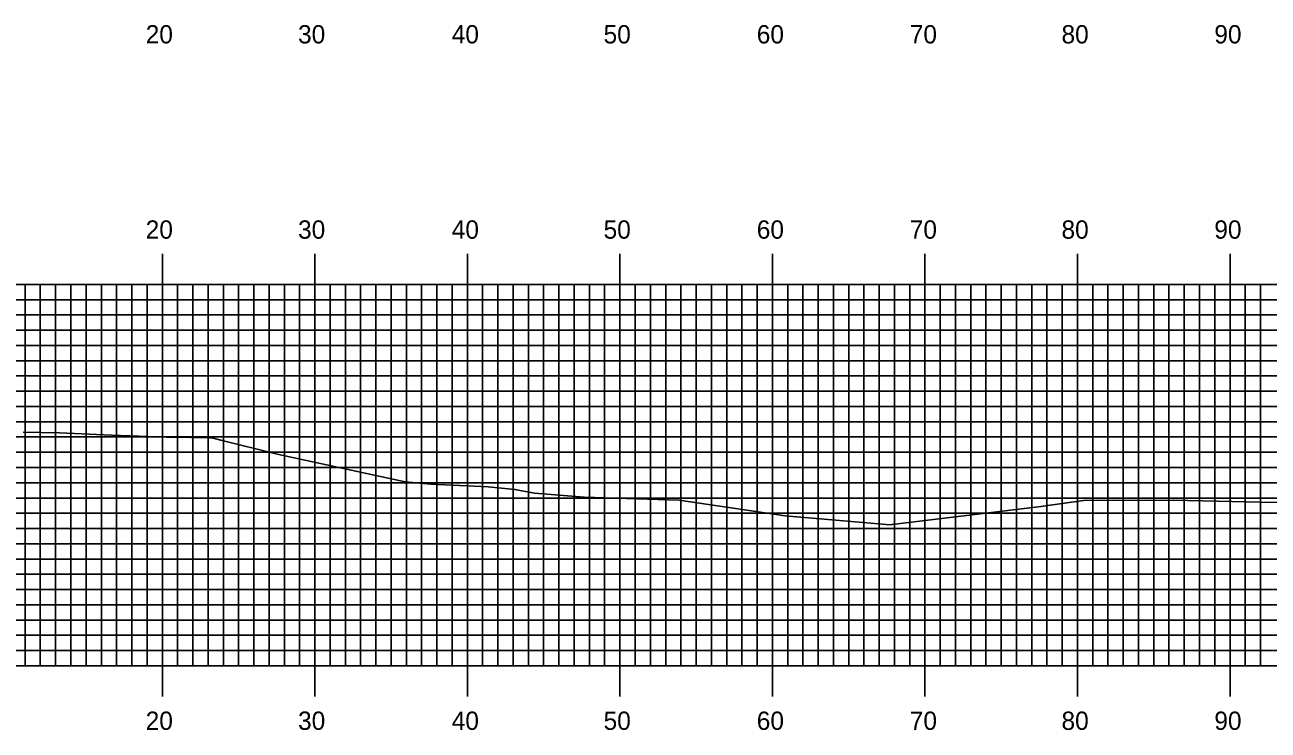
# Model space of a CAD drawing. Extents: x 851300 to 851643, y 366898 to 367118.
# Drawn here: x 851476.5 to 851558, y 366997.3 to 367043.5 of the extents above; entities that cross this region are included whole.
import ezdxf

# ---------------------------------------------------------------- set-up
doc = ezdxf.new("R2010")
doc.units = 0
for name, color, linetype in [('H_V ANNOTATION', 7, 'Continuous'), ('MAJOR', 7, 'Continuous'), ('MINOR', 7, 'Continuous'), ('S_Roadway_Centerline', 7, 'Continuous')]:
    doc.layers.add(name, color=color, linetype=linetype)

msp = doc.modelspace()

# ---------------------------------------------------------------- linework, layer by layer
at = {"layer": 'MAJOR'}
for p, q in [((851485.505, 367028.477), (851485.505, 367026.473)), ((851495.505, 367028.477), (851495.505, 367026.473)), ((851505.505, 367028.477), (851505.505, 367026.473)), ((851515.505, 367028.477), (851515.505, 367026.473)), ((851525.505, 367028.477), (851525.505, 367026.473)), ((851535.505, 367028.477), (851535.505, 367026.473)), ((851545.505, 367028.477), (851545.505, 367026.473)), ((851555.505, 367028.477), (851555.505, 367026.473)), ((851325.505, 367026.473), (851605.505, 367026.473)), ((851325.505, 367026.473), (851605.505, 367026.473)), ((851485.505, 367001.473), (851485.505, 367026.473)), ((851495.505, 367001.473), (851495.505, 367026.473)), ((851505.505, 367001.473), (851505.505, 367026.473)), ((851515.505, 367001.473), (851515.505, 367026.473)), ((851525.505, 367001.473), (851525.505, 367026.473)), ((851535.505, 367001.473), (851535.505, 367026.473)), ((851545.505, 367001.473), (851545.505, 367026.473)), ((851555.505, 367001.473), (851555.505, 367026.473)), ((851325.505, 367021.473), (851605.505, 367021.473)), ((851325.505, 367016.473), (851605.505, 367016.473)), ((851325.505, 367011.473), (851605.505, 367011.473)), ((851325.505, 367006.473), (851605.505, 367006.473)), ((851325.505, 367001.473), (851605.505, 367001.473)), ((851325.505, 367001.473), (851605.505, 367001.473)), ((851485.505, 366999.469), (851485.505, 367001.473)), ((851495.505, 366999.469), (851495.505, 367001.473)), ((851505.505, 366999.469), (851505.505, 367001.473)), ((851515.505, 366999.469), (851515.505, 367001.473)), ((851525.505, 366999.469), (851525.505, 367001.473)), ((851535.505, 366999.469), (851535.505, 367001.473)), ((851545.505, 366999.469), (851545.505, 367001.473)), ((851555.505, 366999.469), (851555.505, 367001.473))]:
    msp.add_line(p, q, dxfattribs=at)
at = {"layer": 'MINOR'}
for p, q in [((851476.505, 367001.473), (851476.505, 367026.473)), ((851477.505, 367001.473), (851477.505, 367026.473)), ((851478.505, 367001.473), (851478.505, 367026.473)), ((851479.505, 367001.473), (851479.505, 367026.473)), ((851480.505, 367001.473), (851480.505, 367026.473)), ((851481.505, 367001.473), (851481.505, 367026.473)), ((851482.505, 367001.473), (851482.505, 367026.473)), ((851483.505, 367001.473), (851483.505, 367026.473)), ((851484.505, 367001.473), (851484.505, 367026.473)), ((851486.505, 367001.473), (851486.505, 367026.473)), ((851487.505, 367001.473), (851487.505, 367026.473)), ((851488.505, 367001.473), (851488.505, 367026.473)), ((851489.505, 367001.473), (851489.505, 367026.473)), ((851490.505, 367001.473), (851490.505, 367026.473)), ((851491.505, 367001.473), (851491.505, 367026.473)), ((851492.505, 367001.473), (851492.505, 367026.473)), ((851493.505, 367001.473), (851493.505, 367026.473)), ((851494.505, 367001.473), (851494.505, 367026.473)), ((851496.505, 367001.473), (851496.505, 367026.473)), ((851497.505, 367001.473), (851497.505, 367026.473)), ((851498.505, 367001.473), (851498.505, 367026.473)), ((851499.505, 367001.473), (851499.505, 367026.473)), ((851500.505, 367001.473), (851500.505, 367026.473)), ((851501.505, 367001.473), (851501.505, 367026.473)), ((851502.505, 367001.473), (851502.505, 367026.473)), ((851503.505, 367001.473), (851503.505, 367026.473)), ((851504.505, 367001.473), (851504.505, 367026.473)), ((851506.505, 367001.473), (851506.505, 367026.473)), ((851507.505, 367001.473), (851507.505, 367026.473)), ((851508.505, 367001.473), (851508.505, 367026.473)), ((851509.505, 367001.473), (851509.505, 367026.473)), ((851510.505, 367001.473), (851510.505, 367026.473)), ((851511.505, 367001.473), (851511.505, 367026.473)), ((851512.505, 367001.473), (851512.505, 367026.473)), ((851513.505, 367001.473), (851513.505, 367026.473)), ((851514.505, 367001.473), (851514.505, 367026.473)), ((851516.505, 367001.473), (851516.505, 367026.473)), ((851517.505, 367001.473), (851517.505, 367026.473)), ((851518.505, 367001.473), (851518.505, 367026.473)), ((851519.505, 367001.473), (851519.505, 367026.473)), ((851520.505, 367001.473), (851520.505, 367026.473)), ((851521.505, 367001.473), (851521.505, 367026.473)), ((851522.505, 367001.473), (851522.505, 367026.473)), ((851523.505, 367001.473), (851523.505, 367026.473)), ((851524.505, 367001.473), (851524.505, 367026.473)), ((851526.505, 367001.473), (851526.505, 367026.473)), ((851527.505, 367001.473), (851527.505, 367026.473)), ((851528.505, 367001.473), (851528.505, 367026.473)), ((851529.505, 367001.473), (851529.505, 367026.473)), ((851530.505, 367001.473), (851530.505, 367026.473)), ((851531.505, 367001.473), (851531.505, 367026.473)), ((851532.505, 367001.473), (851532.505, 367026.473)), ((851533.505, 367001.473), (851533.505, 367026.473)), ((851534.505, 367001.473), (851534.505, 367026.473)), ((851536.505, 367001.473), (851536.505, 367026.473)), ((851537.505, 367001.473), (851537.505, 367026.473)), ((851538.505, 367001.473), (851538.505, 367026.473)), ((851539.505, 367001.473), (851539.505, 367026.473)), ((851540.505, 367001.473), (851540.505, 367026.473)), ((851541.505, 367001.473), (851541.505, 367026.473)), ((851542.505, 367001.473), (851542.505, 367026.473)), ((851543.505, 367001.473), (851543.505, 367026.473)), ((851544.505, 367001.473), (851544.505, 367026.473)), ((851546.505, 367001.473), (851546.505, 367026.473)), ((851547.505, 367001.473), (851547.505, 367026.473)), ((851548.505, 367001.473), (851548.505, 367026.473)), ((851549.505, 367001.473), (851549.505, 367026.473)), ((851550.505, 367001.473), (851550.505, 367026.473)), ((851551.505, 367001.473), (851551.505, 367026.473)), ((851552.505, 367001.473), (851552.505, 367026.473)), ((851553.505, 367001.473), (851553.505, 367026.473)), ((851554.505, 367001.473), (851554.505, 367026.473)), ((851556.505, 367001.473), (851556.505, 367026.473)), ((851557.505, 367001.473), (851557.505, 367026.473)), ((851325.505, 367025.473), (851605.505, 367025.473)), ((851325.505, 367024.473), (851605.505, 367024.473)), ((851325.505, 367023.473), (851605.505, 367023.473)), ((851325.505, 367022.473), (851605.505, 367022.473)), ((851325.505, 367020.473), (851605.505, 367020.473)), ((851325.505, 367019.473), (851605.505, 367019.473)), ((851325.505, 367018.473), (851605.505, 367018.473)), ((851325.505, 367017.473), (851605.505, 367017.473)), ((851325.505, 367015.473), (851605.505, 367015.473)), ((851325.505, 367014.473), (851605.505, 367014.473)), ((851325.505, 367013.473), (851605.505, 367013.473)), ((851325.505, 367012.473), (851605.505, 367012.473)), ((851325.505, 367010.473), (851605.505, 367010.473)), ((851325.505, 367009.473), (851605.505, 367009.473)), ((851325.505, 367008.473), (851605.505, 367008.473)), ((851325.505, 367007.473), (851605.505, 367007.473)), ((851325.505, 367005.473), (851605.505, 367005.473)), ((851325.505, 367004.473), (851605.505, 367004.473)), ((851325.505, 367003.473), (851605.505, 367003.473)), ((851325.505, 367002.473), (851605.505, 367002.473))]:
    msp.add_line(p, q, dxfattribs=at)
at = {"layer": 'S_Roadway_Centerline'}
msp.add_lwpolyline([(851476.378, 367016.793), (851478.759, 367016.736), (851482.162, 367016.603), (851485.758, 367016.465), (851486.137, 367016.461), (851488.621, 367016.408), (851488.828, 367016.404), (851489.35, 367016.265), (851493.039, 367015.342), (851501.426, 367013.537), (851503.117, 367013.378), (851506.86, 367013.209), (851508.62, 367013.037), (851509.901, 367012.791), (851513.153, 367012.523), (851519.385, 367012.325), (851526.343, 367011.304), (851533.224, 367010.718), (851533.354, 367010.747), (851543.109, 367011.911), (851545.903, 367012.303), (851546.352, 367012.321), (851548.587, 367012.311), (851551.78, 367012.333), (851557.549, 367012.209), (851566.205, 367012.101)], dxfattribs=at)

# ---------------------------------------------------------------- texts
at = {"layer": 'H_V ANNOTATION'}
for s, p in [('20', (851484.413, 367042.273)), ('30', (851494.402, 367042.273)), ('40', (851504.477, 367042.273)), ('50', (851514.434, 367042.273)), ('60', (851524.477, 367042.273)), ('70', (851534.509, 367042.273)), ('80', (851544.456, 367042.273)), ('90', (851554.477, 367042.273)), ('20', (851484.413, 367029.473)), ('30', (851494.402, 367029.473)), ('40', (851504.477, 367029.473)), ('50', (851514.434, 367029.473)), ('60', (851524.477, 367029.473)), ('70', (851534.509, 367029.473)), ('80', (851544.456, 367029.473)), ('90', (851554.477, 367029.473)), ('20', (851484.413, 366997.273)), ('30', (851494.402, 366997.273)), ('40', (851504.477, 366997.273)), ('50', (851514.434, 366997.273)), ('60', (851524.477, 366997.273)), ('70', (851534.509, 366997.273)), ('80', (851544.456, 366997.273)), ('90', (851554.477, 366997.273))]:
    msp.add_text(s, height=1.2, dxfattribs=at).set_placement(p)

doc.saveas('drawing.dxf')
